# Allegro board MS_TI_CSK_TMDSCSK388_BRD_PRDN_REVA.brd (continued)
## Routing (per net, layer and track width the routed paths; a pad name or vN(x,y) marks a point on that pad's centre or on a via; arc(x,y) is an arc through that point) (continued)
DM388_DDR0_A1: length 50.2
  TOP w0.102: U6.P7 23.38,18.69 23.1,18.69 v1(22.8,19) 22.21,19.58 21.11,19.58 20.93,19.4 RA4.7 ; U7.AC22 44.07,13.84 43.89,14.02 v1(43.89,14.27) ; U8.P7 v1(23.51,8.39)
  L03_SIG1 w0.102: v1(23.51,8.39) 23.51,7.59 23.91,7.2 23.91,5.84 26.24,3.51 36.71,3.51 36.96,3.51 38.56,5.1 38.56,6.67 38.69,6.8 38.69,7.11 39.25,7.67 39.25,7.86 39.21,7.89 39.21,8.21 39.44,8.43 39.84,8.43 39.99,8.43 40.19,8.23 41.6,8.23 43.64,10.27 43.64,12.22 43.97,12.55 43.97,14.19 v1(43.89,14.27)
  L06_SIG2 w0.102: v1(22.8,19) 21.53,17.73 21.53,10.37 v1(23.51,8.39)
DM388_DDR0_A2: length 49.9
  TOP w0.102: U6.P3 v1(23.51,21.75) ; v1(41.56,13.8) 41.48,13.72 U7.AJ23 ; U8.P3 v1(23.51,11.59)
  L06_SIG2 w0.102: v1(23.51,21.75) 23.82,21.45 23.97,21.45 24.06,21.36 24.06,21.09 23.99,21.02 23.04,21.02 22.94,20.91 22.94,20.71 23.04,20.61 23.41,20.61 23.51,20.51 23.51,18.64 23.93,18.23 23.93,14.91 23.84,14.83 23.66,14.83 23.58,14.74 23.58,14.61 23.66,14.52 23.84,14.52 23.93,14.43 23.93,12.01 v1(23.51,11.59) 23.51,10.27 24.98,8.8 24.98,8.1 25.09,8 26.22,8 26.34,7.87 26.34,7.39 26.45,7.29 26.65,7.29 26.75,7.39 26.75,7.85 26.85,7.95 27.05,7.95 27.16,7.85 27.16,7.39 27.26,7.29 27.46,7.29 27.56,7.39 27.56,7.85 27.66,7.95 27.9,7.95 28,7.85 28,5.89 28.1,5.79 28.3,5.79 28.4,5.89 28.4,7.13 28.51,7.23 28.82,7.23 28.92,7.13 28.92,6.6 29.02,6.5 29.22,6.5 29.33,6.6 29.33,7.13 29.43,7.23 30.45,7.23 30.55,7.13 30.55,6.58 30.66,6.48 30.86,6.48 30.96,6.58 30.96,7.13 31.06,7.23 33.07,7.23 37.15,11.32 38.94,11.32 39.06,11.2 40.29,11.2 40.49,11.41 40.49,12.52 41.15,13.18 41.15,13.39 v1(41.56,13.8)
  BOTTOM w0.102: v1(23.51,21.75) 23.35,21.58 23.35,21.31 22.91,20.88 22.18,20.88 21.83,20.53 RA7.7
DM388_DDR0_A3: length 49.8
  TOP w0.102: U6.N2 v1(24.31,22.55) ; v1(41.45,10.87) 41.48,10.9 U7.AJ27 ; U8.N2 v1(24.31,12.39)
  L03_SIG1 w0.102: v1(24.31,12.39) 24.31,12.42 24.7,12.8 24.7,13.49 23.93,14.25 23.93,14.75 23.83,14.85 23.51,14.85 23.41,14.95 23.41,15.16 23.51,15.26 23.83,15.26 23.93,15.36 23.93,20.53 24.04,20.64 24.57,20.64 24.67,20.74 24.67,20.94 24.57,21.04 24.04,21.04 23.93,21.14 23.93,22.17 v1(24.31,22.55)
  BOTTOM w0.102: v1(24.31,12.39) 23.93,12.01 23.93,10.06 24.24,9.75 27.09,9.75 27.49,10.15 28.26,10.15 28.73,9.68 29.9,9.68 32.21,7.37 32.52,7.37 32.7,7.19 32.7,5.77 32.26,5.33 32.26,4.37 32.36,4.27 37.77,4.27 37.9,4.4 37.9,4.65 37.8,4.75 37.57,4.75 37.47,4.85 37.47,5.05 37.57,5.15 37.83,5.15 37.93,5.25 37.93,5.46 37.83,5.56 37.6,5.56 37.49,5.66 37.49,5.86 37.6,5.97 37.86,5.97 37.95,6.06 37.95,6.28 37.86,6.37 37.55,6.37 37.44,6.47 37.44,6.86 37.42,6.89 37.42,8.07 39.92,10.57 40.59,10.57 40.6,10.56 41.14,10.56 v1(41.45,10.87) ; v1(24.31,22.55) 24.46,22.55 24.57,22.45 24.57,22.28 24.46,22.18 24.06,22.18 23.91,22.33 23.91,23.58 23.77,23.71 RA8.6
DM388_DDR0_A4: length 49.9
  TOP w0.102: U7.AK28 40.01,10.84 39.25,10.07 39.25,10.06 39.25,9.91 39.25,9.91 39.25,9.37 38.77,8.89 38.65,8.89 38.01,8.25 38.01,8.23 37.65,7.87 37.65,6.69 37.88,6.46 38.1,6.46 38.21,6.56 v1(38.21,7.21) ; U8.P8 v1(24.31,6.79) ; U6.P8 v1(23.49,17.78)
  L03_SIG1 w0.102: v1(24.31,6.79) 24.31,6.53 24.7,6.15 24.7,5.56 24.89,5.36 25.04,5.36 25.14,5.47 25.29,5.47 25.43,5.33 25.43,5.18 25.33,5.07 25.33,4.93 25.47,4.79 25.61,4.79 25.72,4.89 25.86,4.89 26.01,4.75 26.01,4.61 25.9,4.5 25.9,4.36 26.04,4.22 26.17,4.22 26.29,4.34 26.47,4.34 26.61,4.2 26.61,4.06 26.54,3.98 26.54,3.91 26.64,3.81 36.83,3.81 38.08,5.06 38.08,6.66 37.32,7.41 37.32,7.58 37.44,7.7 37.78,7.7 37.88,7.8 37.88,8.24 38.41,8.76 38.89,8.76 38.99,8.66 38.99,7.85 38.65,7.5 38.4,7.5 38.21,7.31 v1(38.21,7.21)
  L06_SIG2 w0.102: v1(24.31,6.79) 24.7,7.17 24.7,8.63 23.1,10.23 23.1,14.59 23.01,14.68 22.7,14.68 22.61,14.77 22.61,14.9 22.7,14.99 23.01,14.99 23.1,15.08 23.1,17.38 v1(23.49,17.78)
  BOTTOM w0.102: RA11.5 19.96,17.77 20.23,18.03 21.01,18.03 21.27,17.78 v1(23.49,17.78)
DM388_DDR0_A5: length 49.7
  TOP w0.102: U6.P2 v1(23.51,22.55) ; U7.AH27 41.86,11.22 41.86,10.7 v1(41.47,10.31) ; U8.P2 v1(23.51,12.39)
  L03_SIG1 w0.102: v1(23.51,22.55) 23.1,22.13 23.1,21.59 23.25,21.43 23.25,21.2 23.15,21.1 22.76,21.1 22.66,21 22.66,20.8 22.76,20.69 23.15,20.69 23.25,20.59 23.25,20.39 23.15,20.29 22.76,20.29 22.66,20.19 22.66,19.98 22.76,19.88 23.15,19.88 23.25,19.78 23.25,18.43 23.1,18.27 23.1,14.52 23.9,13.72 23.9,12.77 v1(23.51,12.39)
  BOTTOM w0.102: v1(23.51,22.55) 23.6,22.55 23.7,22.45 23.7,22.31 23.6,22.21 23.24,22.21 23.13,22.31 23.13,22.32 23.1,22.36 23.1,22.74 23.13,22.78 23.13,23.57 23.27,23.71 RA8.7 ; v1(41.47,10.31) 40.09,10.31 37.72,7.94 37.72,7.01 38.26,6.48 38.26,4.12 38.1,3.96 32.11,3.96 31.91,4.17 31.91,7.11 29.7,9.32 28.6,9.32 28.43,9.5 28.43,9.51 28.08,9.86 27.6,9.86 27.26,9.51 27.26,9.5 27.16,9.4 23.32,9.4 23.13,9.59 23.13,12.01 v1(23.51,12.39)
DM388_DDR0_A6: length 49.6
  TOP w0.102: U7.AK30 40.98,9.25 40.08,8.36 39.9,8.36 v1(39.6,8.05) ; U6.R8 v1(22.71,16.95) ; U8.R8 v1(22.71,6.79)
  L03_SIG1 w0.102: v1(39.6,8.05) 39.6,7.59 39.02,7.01 39.02,6.7 38.86,6.55 38.86,4.98 37.09,3.2 36.58,3.2 25.45,3.2 25.35,3.3 25.35,3.86 25.25,3.96 25.05,3.96 24.95,3.86 24.95,3.3 24.85,3.2 24.64,3.2 24.54,3.3 24.54,4.73 24.44,4.83 24.24,4.83 24.13,4.73 24.13,3.3 24.03,3.2 23.8,3.2 23.7,3.3 23.7,4.78 23.6,4.88 23.37,4.88 23.3,4.8 23.3,4.19 23.19,4.09 22.91,4.09 22.81,4.19 22.81,5.41 23.12,5.72 23.12,6.39 v1(22.71,6.79) 23.1,7.17 23.1,9.47 22.99,9.57 22.1,9.57 22,9.67 22,9.87 22.1,9.98 22.99,9.98 23.1,10.08 23.1,13.51 22.33,14.27 22.33,16.31 22.71,16.69 v1(22.71,16.95)
  BOTTOM w0.102: v1(22.71,16.95) 22.33,17.33 21.73,17.33 21.42,17.02 21.42,16.92 20.77,16.27 RA11.8
DM388_DDR0_A7: length 49.8
  TOP w0.102: v1(42.76,13.8) 42.48,13.51 U7.AG23 ; U6.R2 v1(22.71,22.55) ; U8.R2 v1(22.71,12.39)
  L03_SIG1 w0.102: v1(22.71,22.55) 22.3,22.13 22.3,19.98 22.12,19.8 21.7,19.8 21.59,19.7 21.59,19.5 21.7,19.4 22.19,19.4 22.3,19.29 22.3,16.79 22.03,16.53 21.57,16.53 21.42,16.38 21.42,14.05 21.89,13.57 22.07,13.57 22.3,13.35 22.3,13.04 22.71,12.62 v1(22.71,12.39)
  BOTTOM w0.102: v1(22.71,22.55) 22.33,22.93 22.33,23.7 22.16,23.88 22.05,23.88 21.95,23.98 21.95,24.33 22.05,24.44 22.31,24.44 22.42,24.32 RA8.8 ; v1(42.76,13.8) 42.38,13.41 40.66,13.41 40.57,13.5 40.57,13.77 40.49,13.86 40.36,13.86 40.27,13.77 40.27,13.5 40.18,13.41 39.91,13.41 39.82,13.5 39.82,13.73 39.73,13.82 39.6,13.82 39.51,13.73 39.51,13.5 39.42,13.41 36.34,13.41 36.19,13.56 36.19,14.37 36.02,14.54 35.9,14.54 35.8,14.64 35.8,15.69 35.69,15.79 35.49,15.79 35.39,15.69 35.39,14.65 35.28,14.54 35.12,14.54 35.03,14.63 35.03,15.6 34.94,15.69 34.81,15.69 34.72,15.6 34.72,14.7 34.56,14.54 34.44,14.54 34.35,14.63 34.35,14.83 34.26,14.92 34.13,14.92 34.04,14.83 34.04,14.63 33.95,14.54 33.83,14.54 33.74,14.63 33.74,14.83 33.65,14.92 33.52,14.92 33.43,14.83 33.43,14.63 33.34,14.54 32.3,14.54 32.21,14.63 32.21,15.48 32.12,15.57 31.99,15.57 31.9,15.48 31.9,14.63 31.81,14.54 22.49,14.54 22.28,14.34 22.28,13.54 22.33,13.49 22.33,12.78 v1(22.71,12.39)
DM388_DDR0_A8: length 49.4
  TOP w0.102: U8.T8 v1(21.91,6.79) ; v1(39.35,6.34) 39.04,6.64 39.04,8.13 39.65,8.75 39.65,9.43 39.65,9.43 39.65,9.74 39.65,9.74 39.65,9.9 40.1,10.34 U7.AL29 ; RA4.5 19.81,17.33 20.17,16.97 21.9,16.97 v1(21.91,16.95) U6.T8
  L03_SIG1 w0.102: v1(21.91,6.79) 22.33,6.38 22.33,4.09 23.52,2.9 36.46,2.9 37.21,2.9 38.79,4.47 40.31,4.47 40.82,4.98 40.82,5.79 40.57,6.04 40.57,7.32 40.46,7.42 40.21,7.42 40.11,7.32 40.11,6.68 39.98,6.56 39.98,6.54 39.78,6.34 v1(39.35,6.34)
  BOTTOM w0.102: v1(21.91,16.95) 21.06,16.1 21.06,9.96 21.16,9.86 21.85,9.86 21.95,9.76 21.95,9.56 21.85,9.45 21.16,9.45 21.06,9.35 21.06,7.06 21.33,6.79 v1(21.91,6.79)
DM388_DDR0_A9: length 49.6
  TOP w0.102: v1(38.45,7.99) 38.94,8.48 38.94,8.65 39.45,9.16 39.45,9.34 39.45,9.98 39.45,9.99 40.09,10.64 40.68,10.64 U7.AK29 ; U6.R3 v1(22.71,21.75) ; U8.R3 v1(22.71,11.59)
  L06_SIG2 w0.102: v1(22.71,11.59) 22.69,11.59 22.31,11.97 22.31,17.42 23.2,18.31 23.2,19.42 23.09,19.52 22.38,19.52 22.28,19.62 22.28,19.83 22.38,19.93 22.92,19.93 23.02,20.03 23.02,20.23 22.92,20.34 22.38,20.34 22.28,20.44 22.28,20.64 22.71,21.08 v1(22.71,21.75)
  BOTTOM w0.102: v1(22.71,11.59) 22.71,9.04 22.84,8.92 27.28,8.92 27.46,9.09 27.46,9.43 27.68,9.65 28,9.65 28.22,9.43 28.22,9.09 28.32,8.99 28.86,8.99 29.13,8.72 29.13,8.21 30.15,7.19 30.82,7.19 31.12,6.89 31.12,4.06 31.53,3.66 38.23,3.66 38.76,4.18 38.76,7.68 v1(38.45,7.99) ; RA7.6 22.04,21.03 22.22,21.21 22.87,21.21 23.02,21.36 23.02,21.92 22.91,22.02 22.79,22.02 22.69,21.92 22.69,21.78 v1(22.71,21.75)
DM388_DDR0_A10: length 49.4
  TOP w0.102: v1(43.53,13.82) 43.98,13.37 U7.AD23 ; U6.L7 v1(25.91,17.75) ; U8.L7 v1(25.91,7.59)
  L03_SIG1 w0.102: v1(25.91,7.59) 25.91,8.02 25.91,8.03 25.91,10.16 27.11,11.35 27.11,13.46 26.66,13.91 26.66,15.48 26.33,15.81 26.33,18.42 26.23,18.52 26.02,18.52 25.91,18.42 v1(25.91,17.75)
  L06_SIG2 w0.102: v1(43.53,13.82) 43.53,13.24 42.76,12.47 41.51,12.47 41.51,12.45 41.02,11.96 41.02,11.36 40.31,10.65 37.48,10.65 35.89,9.07 35.89,8.67 35.15,7.93 35.15,5.6 35.13,5.59 35.13,4.47 35.01,4.35 25.24,4.35 25.14,4.45 25.14,4.95 25.04,5.06 24.84,5.06 24.73,4.95 24.73,4.45 24.63,4.35 24.4,4.35 24.24,4.52 24.24,5.33 24.39,5.49 25.35,5.49 25.53,5.67 25.53,7.21 v1(25.91,7.59)
  BOTTOM w0.102: RA10.8 25.12,19.37 25.02,19.27 25.02,19.1 25.12,19 25.76,19 26.08,18.68 26.08,18.53 25.91,18.37 v1(25.91,17.75)
DM388_DDR0_A11: length 48.3
  TOP w0.102: U7.AK24 40.69,12.55 39.7,12.55 39.42,12.83 39.35,12.83 39.04,12.83 38.33,12.12 v1(38.33,10.14) ; U6.R7 22.65,18.62 22.64,18.62 22.55,18.71 22.12,18.71 21.95,18.54 v1(21.52,18.54) 21.16,18.9 RA4.6 ; U8.R7 v1(22.71,8.39)
  L06_SIG2 w0.102: v1(21.52,18.54) 21.11,18.14 21.11,9.25 21.97,8.39 v1(22.71,8.39) 22.33,8.01 22.33,5.26 22.36,5.23 22.36,5 22.24,4.88 21.89,4.88 21.77,4.76 21.77,4.52 21.89,4.4 22.24,4.4 22.36,4.28 22.36,3.91 22.54,3.73 36.39,3.73 37.22,4.56 37.22,9.3 37.16,9.37 37.16,9.78 37.51,10.14 v1(38.33,10.14)
DM388_DDR0_A12: length 51.8
  TOP w0.102: U6.N7 24.86,18.3 24.86,18.61 ; 24.86,18.61 v1(24.91,18.65) ; 24.86,18.61 24.6,18.61 23.31,19.9 RA4.8 ; U7.AH23 41.98,13.58 v1(42.19,13.8) ; U8.N7 v1(24.31,8.39)
  L03_SIG1 w0.102: v1(24.91,18.65) 24.91,18.88 24.9,18.89 24.9,18.9 24.77,19.03 24.54,19.03 24.44,18.92 24.44,17.4 24.73,17.1 24.73,16.76 24.96,16.53 25.27,16.53 25.5,16.31 25.5,15.5 25.84,15.16 25.84,12.85 25.53,12.55 25.53,9.61 v1(24.31,8.39) 25.53,7.18 25.53,6.6 26.03,6.11 26.03,5.73 27.33,4.43 36.51,4.43 37.28,5.2 37.46,5.37 37.46,6.41 36.68,7.19 36.68,8.18 37.6,9.09 37.85,9.09 38.18,9.42 38.56,9.42 39.15,10.01 40.31,10.01 40.52,9.81 40.52,8.87 40.69,8.69 41.48,8.69 43.23,10.44 43.23,12.76 v1(42.19,13.8)
DM388_DDR0_A13: length 50.3
  TOP w0.102: v1(36.73,9.07) 37.05,9.39 37.05,9.72 37.35,10.02 37.35,12.15 38.99,13.79 40.52,13.79 U7.AK23 ; U6.T3 v1(21.91,21.75) ; U8.T3 v1(21.91,11.59)
  L03_SIG1 w0.102: v1(21.91,21.75) 21.14,20.97 21.14,20.77 21.24,20.67 21.47,20.67 21.57,20.57 21.57,20.36 21.47,20.26 21.26,20.26 21.14,20.14 21.14,18.22 21.33,18.03 21.33,17 20.86,16.53 20.86,12.93 20.98,12.81 22.03,12.81 22.3,12.55 22.3,11.97 v1(21.91,11.59)
  L06_SIG2 w0.102: v1(21.91,11.59) 21.91,10.86 23.9,8.88 23.9,4.4 24.26,4.04 35.31,4.04 35.44,4.17 35.44,7.77 v1(36.73,9.07)
  BOTTOM w0.102: RA7.5 20.62,21.53 20.54,21.6 20.54,21.89 20.71,22.06 21.68,22.06 21.77,22.15 22.2,22.15 22.31,22.05 22.31,21.82 22.2,21.72 21.95,21.72 v1(21.91,21.75)
DM388_DDR0_A14: length 48.1
  TOP w0.102: v1(20.66,17.63) 21.79,17.63 U6.T7 ; U7.AL23 40.28,13.54 39.2,13.54 37.83,12.17 37.83,9.76 v1(37.65,9.58) ; U8.T7 v1(21.91,7.59)
  L03_SIG1 w0.102: v1(20.66,17.63) 20.22,17.19 20.22,16.87 20.2,16.84 20.2,8.48 21.09,7.59 v1(21.91,7.59)
  L06_SIG2 w0.102: v1(37.65,9.58) 37.65,4.42 36.58,3.35 22.15,3.35 21.11,4.4 21.11,7.27 21.44,7.59 v1(21.91,7.59)
  BOTTOM w0.102: RA11.6 20.39,17.27 20.52,17.14 20.66,17.14 20.96,17.43 20.96,17.58 20.86,17.68 20.71,17.68 v1(20.66,17.63)
DM388_DDR0_BA0: length 49.2
  TOP w0.102: U7.AK26 40.68,12.14 39.84,12.14 v1(39.32,11.62) ; U8.M2 v1(25.11,12.39) ; U6.M2 v1(25.11,22.55)
  L06_SIG2 w0.102: v1(39.32,11.62) 37,11.62 33.38,8 32.68,8 32.58,7.9 32.58,7.62 32.48,7.52 32.28,7.52 32.17,7.62 32.17,7.9 32.07,8 31.87,8 31.77,7.9 31.77,7.62 31.67,7.52 31.46,7.52 31.36,7.62 31.36,7.9 31.26,8 30.23,8 30.13,7.9 30.13,7.62 30.03,7.52 29.83,7.52 29.73,7.62 29.73,7.9 29.63,8 29.26,8 29.13,8.13 29.13,8.77 28.88,9.02 28.4,9.02 28.3,9.12 28.3,9.58 28.15,9.73 27.44,9.73 27.33,9.63 27.33,8.92 27.23,8.81 25.99,8.81 25.89,8.71 25.89,8.41 25.78,8.31 25.58,8.31 25.48,8.41 25.48,8.99 25.38,9.09 25.2,9.09 25.1,9.2 25.1,9.4 25.2,9.5 25.38,9.5 25.48,9.6 25.48,9.83 25.38,9.93 24.24,9.93 24.11,10.07 24.11,10.21 24.21,10.31 25.66,10.31 25.73,10.39 25.73,10.59 25.62,10.7 23.93,10.7 23.83,10.8 23.83,11.01 23.93,11.11 24.62,11.11 24.72,11.21 24.72,11.97 25.11,12.37 v1(25.11,12.39) 25.11,12.54 25.51,12.93 25.51,14.22 25.42,14.31 25.25,14.31 25.16,14.4 25.16,14.52 25.25,14.61 25.42,14.61 25.51,14.7 25.51,14.83 25.42,14.92 25.25,14.92 25.16,15 25.16,15.13 25.25,15.22 25.42,15.22 25.51,15.31 25.51,18.05 25.5,18.06 25.5,18.76 24.73,19.52 24.73,20.04 24.84,20.14 25.33,20.14 25.43,20.24 25.43,20.45 25.33,20.55 24.84,20.55 24.73,20.65 24.73,22.17 v1(25.11,22.55)
  BOTTOM w0.102: v1(25.11,22.55) 24.72,22.95 24.72,24.64 24.62,24.74 24.35,24.74 24.27,24.67 RA8.5
DM388_DDR0_BA1: length 51.7
  TOP w0.102: v1(42.77,14.4) 43.15,14.02 43.15,13.51 U7.AF23 ; U8.N8 v1(24.31,7.59) ; U6.N8 v1(24.31,16.95)
  L03_SIG1 w0.102: v1(24.31,16.95) 24.31,16.69 24.72,16.29 24.72,15.19 24.82,15.09 25.25,15.09 25.38,14.96 25.38,14.71 25.28,14.61 24.49,14.61 24.39,14.5 24.39,14.28 24.59,14.07 25.3,14.07 25.53,13.84 25.53,13.07 25.23,12.77 24.96,12.77 24.7,12.51 24.7,10.04 23.93,9.27 23.93,7.97 v1(24.31,7.59) 24.7,7.21 24.7,6.63 24.96,6.37 25.27,6.37 25.61,6.03 25.61,5.66 27.15,4.12 36.63,4.12 37.76,5.25 37.76,6.09 37.76,6.54 36.99,7.32 36.99,7.95 37.82,8.79 37.97,8.79 38.25,9.07 39.49,9.07 39.92,8.64 40.21,8.64 40.42,8.43 41.52,8.43 43.44,10.35 43.44,13.13 43.15,13.42 43.15,14.02 v1(42.77,14.4)
  BOTTOM w0.102: RA11.7 20.39,16.77 20.52,16.64 20.63,16.64 21.54,17.55 23.12,17.55 23.72,16.95 v1(24.31,16.95)
DM388_DDR0_BA2: length 49.4
  TOP w0.102: v1(42.13,11.83) 41.98,11.98 U7.AH25 ; U6.M3 v1(25.11,21.75) ; U8.M3 v1(25.11,11.59)
  L06_SIG2 w0.102: v1(25.11,21.75) 25.71,21.16 25.71,20.68 25.81,20.58 26.17,20.58 26.27,20.47 26.27,20.27 26.17,20.17 25.81,20.17 25.71,20.07 25.71,19.87 25.81,19.76 26.17,19.76 26.27,19.66 26.27,19.46 26.17,19.36 25.81,19.36 25.71,19.26 25.71,18.97 26.3,18.39 26.3,16.77 25.82,16.29 25.82,13.72 25.72,13.62 25.72,12.84 25.51,12.63 25.51,11.98 v1(25.11,11.59)
  BOTTOM w0.102: v1(25.11,11.59) 24.67,11.15 24.41,11.15 24.31,11.05 24.31,10.24 24.51,10.03 26.94,10.03 27.26,10.35 29.68,10.35 32.39,7.65 34.09,7.65 34.33,7.4 34.33,5.83 34.7,5.46 34.7,4.68 34.8,4.57 35.03,4.57 35.13,4.68 35.13,5.28 35.23,5.39 35.44,5.39 35.54,5.28 35.54,4.68 35.64,4.57 35.85,4.57 35.95,4.68 35.95,5.28 36.05,5.39 36.25,5.39 36.36,5.28 36.36,4.68 36.46,4.57 37.01,4.57 37.15,4.71 37.15,6.33 37.11,6.37 37.11,8.19 39.84,10.92 40.64,10.92 41.1,11.38 41.68,11.38 v1(42.13,11.83) ; v1(25.11,21.75) 25.12,21.74 25.12,21.54 25.02,21.44 24.9,21.44 24.74,21.59 24.74,22.05 24.85,22.15 25.45,22.15 25.53,22.07 25.53,21.42 25.65,21.3 RA10.5
DM388_DDR0_CASN: length 49
  TOP w0.102: U6.K3 v1(26.71,21.75) ; U7.AK25 39.33,12.34 39.22,12.45 v1(39.2,12.45) ; U8.K3 v1(26.71,11.59)
  L06_SIG2 w0.102: v1(26.71,11.59) 26.33,11.97 26.33,13.38 27.44,14.48 27.44,14.68 27.56,14.8 27.78,14.8 27.9,14.92 27.9,15.77 27.79,15.87 27.4,15.87 27.3,15.97 27.3,16.18 27.4,16.28 27.79,16.28 27.9,16.38 27.9,16.61 27.79,16.71 27.74,16.71 27.64,16.81 27.64,17.01 27.74,17.12 27.79,17.12 27.9,17.22 27.9,18.47 27.61,18.75 27.61,20.42 26.71,21.32 v1(26.71,21.75)
  BOTTOM w0.102: RA6.7 25.94,23.36 26.32,22.99 26.32,21.87 26.44,21.75 v1(26.71,21.75) ; v1(39.2,12.45) 38.76,12.45 38.59,12.27 38.59,11.66 38.48,11.56 38.08,11.56 37.98,11.66 37.98,12.61 37.88,12.71 37.55,12.71 37.44,12.6 37.44,11.02 37.27,10.85 37.06,10.85 36.99,10.92 36.99,12.19 36.88,12.29 36.66,12.29 36.55,12.19 36.55,10.39 36.45,10.29 36.16,10.29 36.06,10.39 36.06,11.41 35.96,11.51 35.75,11.51 35.65,11.41 35.65,10.39 35.55,10.29 35.28,10.29 35.18,10.39 35.18,10.64 35.08,10.75 34.87,10.75 34.77,10.64 34.77,10.39 34.67,10.29 34.44,10.29 34.34,10.39 34.34,11.08 34.24,11.18 34.04,11.18 33.93,11.08 33.93,10.39 33.83,10.29 33.63,10.29 33.53,10.39 33.53,11.08 33.43,11.18 33.22,11.18 33.12,11.08 33.12,10.39 33.02,10.29 32.82,10.29 32.71,10.39 32.71,11.08 32.61,11.18 32.41,11.18 32.31,11.08 32.31,9.85 32.24,9.78 31.96,9.78 31.86,9.88 31.86,11.08 31.75,11.18 31.53,11.18 31.42,11.08 31.42,10.34 31.32,10.24 31.12,10.24 31,10.35 31,11.02 30.9,11.13 27.18,11.13 v1(26.71,11.59)
DM388_DDR0_CKE: length 50.3
  TOP w0.102: U6.K9 v1(26.71,16.15) ; v1(43.33,14.4) 43.44,14.4 43.69,14.65 43.79,14.65 U7.AD20 ; U8.K9 v1(26.71,5.99)
  L03_SIG1 w0.102: v1(26.71,16.15) 27.02,15.85 27.02,15.63 27.18,15.47 27.41,15.47 27.51,15.37 27.51,15.04 27.41,14.94 27.07,14.94 26.97,14.84 26.97,14.64 27.07,14.54 27.34,14.54 27.44,14.43 27.44,13.55 27.51,13.47 27.51,13.08 27.94,12.65 27.94,11.18 26.33,9.57 26.33,8 27.13,7.2 27.13,6.41 v1(26.71,5.99)
  L06_SIG2 w0.102: v1(43.33,14.4) 43.21,14.28 43.21,14.12 43.15,14.07 43.15,13.44 42.69,12.98 41.38,12.98 40.69,12.29 40.69,11.32 40.3,10.92 39.03,10.92 38.94,11.01 37.28,11.01 34.33,8.07 34.33,4.87 34.12,4.66 29.34,4.66 29.24,4.76 29.24,5.28 29.14,5.39 28.93,5.39 28.83,5.28 28.83,4.76 28.73,4.66 28.53,4.66 28.43,4.76 28.43,5.28 28.32,5.39 28.12,5.39 28.02,5.28 28.02,4.76 27.92,4.66 27.72,4.66 27.61,4.76 27.61,5.28 27.51,5.39 27.31,5.39 27.21,5.28 27.21,4.76 27.11,4.66 26.9,4.66 26.8,4.76 26.8,5.28 26.7,5.39 26.5,5.39 26.39,5.28 26.39,4.76 26.29,4.66 26.06,4.66 25.91,4.81 25.91,5.87 26.04,5.99 v1(26.71,5.99)
  BOTTOM w0.102: RA10.7 25.91,19.87 26.32,19.46 26.32,16.55 v1(26.71,16.15)
DM388_DDR0_CLK: length 49.9
  TOP w0.102: U6.J7 v1(27.51,17.75) ; U8.J7 v1(27.51,8.39) ; U7.AL27 39.71,11.34 39.64,11.26 39.49,11.26 38.82,10.59 38.82,9.94 38.48,9.6 38.35,9.6 36.89,8.13 35.46,8.13 35.2,7.86 35.2,7.28 35.46,7.01 36.74,7.01 36.89,6.86 36.89,6.41 37.16,6.14 37.16,4.39 37.04,4.27 34.13,4.27 34.03,4.37 34.03,4.63 34.16,4.75 35.89,4.75 36.17,5.03 36.17,5.46 36.23,5.51 36.71,5.51 36.78,5.59 36.78,5.78 v1(36.67,5.89)
  L03_SIG1 w0.102: v1(36.67,5.89) 36.62,5.85 36.48,5.85 36.38,5.95 36.38,6.28 36.01,6.66 35.51,6.66 35.18,6.33 35.18,5.65 35.01,5.48 28.53,5.48 28.32,5.68 28.32,7.29 27.81,7.8 27.47,7.8 27.13,8.14 27.13,8.31 27.22,8.39 27.45,8.39 ; v1(27.51,17.75) 27.41,17.75 27.26,17.6 27.26,17.45 28.05,16.66 28.05,15.91 28.32,15.63 29.2,15.63 29.49,15.34 29.49,14.86 29.2,14.57 28.32,14.57 28.25,14.49 28.25,13.84 28.68,13.41 28.68,10.87 27.25,9.44 27.25,8.59 27.45,8.39 ; 27.45,8.39 v1(27.51,8.39)
  BOTTOM w0.102: v1(27.51,17.75) 27.44,17.75 27.33,17.85 27.33,18.15 27.44,18.25 27.92,18.25 28.19,18.51 28.19,18.89 27.97,19.11 27.97,19.33 28.29,19.65 R107.1
DM388_DDR0_CLKN: length 49.9
  TOP w0.102: v1(35.96,5.89) 35.89,5.83 35.89,5.15 35.78,5.03 34.04,5.03 33.75,4.74 33.75,4.25 34.01,3.99 37.15,3.99 37.44,4.28 37.44,6.25 37.17,6.52 37.17,6.98 36.86,7.29 35.58,7.29 35.48,7.39 35.48,7.75 35.58,7.85 37,7.85 38.47,9.32 38.59,9.32 39.02,9.74 39.02,10.44 39.64,11.06 40.7,11.06 U7.AK27 ; U6.K7 v1(26.71,17.75) ; U8.K7 v1(26.71,8.39)
  L03_SIG1 w0.102: v1(26.71,17.75) 26.93,17.54 26.93,17.31 27.72,16.53 27.72,15.78 28.19,15.3 29.06,15.3 29.16,15.2 29.16,14.99 29.07,14.9 28.19,14.9 27.92,14.63 27.92,13.71 28.35,13.28 28.35,11.01 26.92,9.58 26.92,8.55 26.76,8.39 v1(26.71,8.39) 26.8,8.31 26.8,8 27.33,7.47 27.68,7.47 27.99,7.15 27.99,5.54 28.39,5.15 35.15,5.15 35.51,5.51 35.51,6.19 35.65,6.33 35.87,6.33 36.05,6.15 36.05,5.98 v1(35.96,5.89)
  BOTTOM w0.102: R108.1 27.42,19.65 27.69,19.38 27.69,18.99 27.91,18.77 27.91,18.63 27.81,18.53 27.32,18.53 27.05,18.26 27.05,17.96 26.85,17.75 v1(26.71,17.75)
DM388_DDR0_CS0N: length 49.4
  TOP w0.102: U7.AB21 44.51,14.34 v1(44.47,14.3) ; U8.L2 v1(25.91,12.39) ; U6.L2 v1(25.91,22.55)
  L06_SIG2 w0.102: v1(25.91,22.55) 26.3,22.17 26.3,21.24 27.1,20.44 27.1,20.09 26.99,19.99 26.67,19.99 26.57,19.89 26.57,19.68 26.67,19.58 26.99,19.58 27.1,19.48 27.1,19.28 26.99,19.18 26.67,19.18 26.57,19.07 26.57,18.87 26.67,18.77 26.99,18.77 27.1,18.67 27.1,15.85 26.72,15.47 26.72,14.29 25.93,13.51 25.93,12.41 v1(25.91,12.39)
  BOTTOM w0.102: v1(25.91,22.55) 25.56,22.91 25.56,23.5 25.33,23.72 25.23,23.72 25.02,23.93 25.02,24.56 25.15,24.69 25.33,24.69 25.44,24.58 RA6.8 ; v1(44.47,14.3) 44.17,13.99 44.17,12.72 43.82,12.37 41.38,12.37 40.25,11.24 39.6,11.24 39.31,10.95 38.28,10.95 37.16,9.83 37.16,9.38 37.21,9.33 37.21,8.73 36.81,8.32 36.81,6.49 36.71,6.39 36.35,6.39 36.25,6.49 36.25,7.93 36.15,8.03 35.92,8.03 35.82,7.93 35.82,7.11 35.72,7.01 35.51,7.01 35.41,7.11 35.41,7.93 35.31,8.03 32.47,8.03 32.36,8.13 32.36,8.92 32.02,9.26 31.3,9.26 30,10.55 26.86,10.55 26.7,10.39 25.64,10.39 25.53,10.49 25.53,12.01 v1(25.91,12.39)
DM388_DDR0_DQ0: length 18.5
  TOP w0.102: U7.AL9 40.21,20.61 39.15,20.61 38.99,20.45 33.63,20.45 33.49,20.58 33.49,20.8 33.39,20.91 33.19,20.91 33.09,20.8 33.09,20.58 32.99,20.48 32.78,20.48 32.68,20.58 32.68,20.8 32.58,20.91 32.37,20.91 32.27,20.8 32.27,20.58 32.17,20.48 31.97,20.48 31.86,20.58 31.86,20.8 31.76,20.91 31.56,20.91 31.46,20.8 31.46,20.58 30.86,19.99 28.25,19.99 28.15,20.09 28.15,20.27 28.25,20.37 30.63,20.37 31.11,20.85 U6.E3
DM388_DDR0_DQ1: length 18.9
  TOP w0.102: v1(38.04,19.82) 38.35,20.12 39,20.12 39.15,20.27 40.06,20.27 40.27,20.06 40.7,20.06 U7.AK9 ; U6.F7 v1(30.31,19.18)
  L03_SIG1 w0.102: v1(30.31,19.18) 30.08,18.94 30.08,18.8 30.15,18.72 31.32,18.72 31.83,19.23 31.83,19.61 31.93,19.71 32.14,19.71 32.24,19.61 32.24,19.41 32.34,19.3 32.54,19.3 32.64,19.41 32.64,19.61 32.75,19.71 32.95,19.71 33.05,19.61 33.05,19.41 33.15,19.3 33.36,19.3 33.46,19.41 33.46,19.61 33.56,19.71 33.76,19.71 33.86,19.61 33.86,19.41 33.97,19.3 34.17,19.3 34.27,19.41 34.27,19.61 34.37,19.71 34.57,19.71 34.68,19.61 34.68,19.41 34.78,19.3 35.23,19.3 35.69,19.76 36.05,19.76 36.15,19.66 36.15,19.49 36.29,19.36 36.46,19.36 36.56,19.46 36.56,19.66 36.66,19.76 36.94,19.76 37.04,19.66 37.04,19.53 37.34,19.23 38.61,19.23 38.76,19.38 38.76,19.97 38.6,20.13 38.12,20.13 38.04,20.06 v1(38.04,19.82)
DM388_DDR0_DQ2: length 18.9
  TOP w0.102: U6.F2 30.74,21.73 30.74,21.06 30.25,20.57 28.02,20.57 27.92,20.47 27.92,19.89 28.02,19.79 31.08,19.79 31.2,19.79 31.55,20.14 36.45,20.14 36.58,20.02 37.16,20.02 37.88,19.3 38.54,19.3 39.02,19.79 39.09,19.79 39.3,19.99 39.96,19.99 40.11,19.84 U7.AK10
DM388_DDR0_DQ3: length 18.7
  TOP w0.102: U7.AJ11 41.48,19.71 v1(41.56,19.79) ; U6.F8 v1(30.69,17.73)
  L03_SIG1 w0.102: v1(41.56,19.79) 41.13,19.79 40,18.67 39.12,18.67 39.07,18.62 37.6,18.62 37.25,18.26 35.69,18.26 35.23,18.72 32.06,18.72 31.5,18.16 30.46,18.16 29.53,17.24 29.53,15.99 29.78,15.75 30.23,15.75 30.33,15.85 30.33,17.37 v1(30.69,17.73)
DM388_DDR0_DQ4: length 18.4
  TOP w0.102: U6.H3 v1(29.11,21.75) ; v1(42.19,19.77) 41.98,19.55 U7.AH11
  L06_SIG2 w0.102: v1(42.19,19.77) 41.83,19.41 41.18,19.41 40.34,20.24 37.32,20.24 37.31,20.25 36.89,20.25 36,21.14 36,21.64 35.21,22.43 35.21,23.55 35.02,23.73 32.96,23.73 32.95,23.72 32.91,23.72 32.7,23.51 32.7,23.19 32.43,22.93 29.76,22.93 29.53,22.71 29.53,22.17 v1(29.11,21.75)
DM388_DDR0_DQ5: length 18.7
  TOP w0.102: U6.H8 v1(29.14,16.93) ; v1(43.91,19.84) 43.98,19.9 U7.AD9
  L03_SIG1 w0.102: v1(29.14,16.93) 29.14,17.36 30.19,18.42 31.4,18.42 32.03,19.05 35.34,19.05 35.74,18.65 37.09,18.65 37.37,18.92 39.94,18.92 40.54,19.53 40.54,19.9 41.4,20.76 42.99,20.76 v1(43.91,19.84)
DM388_DDR0_DQ6: length 18.8
  TOP w0.102: U6.G2 v1(29.91,22.55) ; v1(42.76,19.77) 42.98,19.55 U7.AF11
  L06_SIG2 w0.102: v1(29.91,22.55) 29.91,21.68 30.22,21.37 32.59,21.37 32.73,21.51 32.73,22.75 32.92,22.93 32.96,22.93 34.39,22.93 34.99,22.34 35.34,21.99 35.34,21.87 35.69,21.52 35.69,21.02 35.87,20.84 35.87,20.84 36.76,19.95 37.18,19.95 37.79,19.34 38.24,19.34 38.7,19.8 40.2,19.8 40.8,19.2 41.09,19.2 42.2,19.2 v1(42.76,19.77)
DM388_DDR0_DQ7: length 18.6
  TOP w0.102: U7.AL12 40.32,18.84 40.24,18.92 39.06,18.92 38.99,19 37.72,19 37.05,19.67 36.33,19.67 36.19,19.81 31.65,19.81 31.4,19.56 26.17,19.56 26.01,19.41 26.01,18.8 26.17,18.64 28.22,18.64 U6.H7
DM388_DDR0_DQ8: length 13.8
  TOP w0.102: U7.AJ12 41.48,18.45 v1(41.56,18.37) ; U6.D7 v1(31.54,17.78)
  L03_SIG1 w0.102: v1(31.54,17.78) 31.23,17.47 31.07,17.47 30.94,17.34 30.94,16.82 31.22,16.54 35.67,16.54 36.2,17.07 37.44,17.07 37.87,17.5 40.11,17.5 40.98,18.37 v1(41.56,18.37)
DM388_DDR0_DQ9: length 14.1
  TOP w0.102: U6.C3 v1(33.11,21.75) ; U7.AG12 42.48,18.62 v1(42.73,18.37)
  BOTTOM w0.102: v1(33.11,21.75) 32.77,21.41 32.77,19.43 33.57,18.63 38.94,18.63 39.1,18.79 42.3,18.79 v1(42.73,18.37)
DM388_DDR0_DQ10: length 14
  TOP w0.102: v1(43.84,19.28) 43.98,19.14 U7.AD12 ; U6.C8 v1(33.1,16.97)
  L03_SIG1 w0.102: v1(43.84,19.28) 43.38,18.82 43,18.82 42.9,18.92 42.9,19.18 42.79,19.28 42.59,19.28 42.49,19.18 42.49,18.92 42.39,18.82 42.16,18.82 42.06,18.92 42.06,19.15 41.96,19.25 41.75,19.25 41.65,19.15 41.65,18.92 41.55,18.82 41,18.82 39.98,17.81 37.75,17.81 37.31,17.37 36.73,17.37 34.52,17.37 34.12,16.97 v1(33.1,16.97)
DM388_DDR0_DQ11: length 14.4
  TOP w0.102: U7.AB12 v1(44.55,18.84) ; U6.C2 v1(33.11,22.55)
  L06_SIG2 w0.102: v1(33.11,22.55) 33.53,22.13 34.9,22.13 35.14,21.9 35.14,21.69 35.31,21.51 35.31,20.96 36.64,19.62 37.06,19.62 37.76,18.92 39.06,18.92 39.06,18.92 39.94,18.92 39.97,18.95 43.58,18.95 43.61,18.95 43.69,18.88 43.73,18.84 v1(44.55,18.84)
DM388_DDR0_DQ12: length 13.9
  TOP w0.102: U6.A7 v1(34.71,17.75) ; v1(39.88,18.29) 39.93,18.34 U7.AK13
  L03_SIG1 w0.102: v1(34.71,17.75) 34.28,17.75 33.88,17.35 32.13,17.35 31.98,17.5 31.98,18.26 32.13,18.42 35.06,18.42 35.72,17.75 37.26,17.75 37.8,18.29 v1(39.88,18.29)
DM388_DDR0_DQ13: length 14.2
  TOP w0.102: U6.A2 34.72,21.74 ; v1(43.91,18.37) 43.94,18.34 U7.AC13
  TOP w0.14: 34.72,21.74 v1(34.76,21.74)
  L06_SIG2 w0.102: v1(43.91,18.37) 43.6,18.68 43.53,18.75 43.49,18.75 40.05,18.75 40.02,18.72 39.65,18.72 38.97,18.03 35.31,18.03 35.06,18.28 35.06,21.44 v1(34.76,21.74)
DM388_DDR0_DQ14: length 14
  TOP w0.102: U7.AL14 40.21,17.57 39.65,17.57 39.14,18.09 36.94,18.09 36.73,18.29 36.04,18.29 34.83,19.51 32.59,19.51 32.49,19.41 32.49,19.13 32.39,19.03 32.19,19.03 32.08,19.13 32.08,19.41 31.98,19.51 31.75,19.51 31.65,19.41 31.65,18.75 31.75,18.64 32.21,18.64 32.31,18.54 32.31,17.91 32.47,17.75 33.12,17.75 U6.B8
DM388_DDR0_DQ15: length 14.2
  TOP w0.102: v1(35.79,19.28) 36.22,19.28 36.33,19.17 36.33,18.97 36.71,18.6 36.85,18.6 37.06,18.39 39.22,18.39 39.73,17.88 40.09,17.88 40.34,18.14 40.68,18.14 U7.AK14 ; U6.A3 34.01,21.05
  TOP w0.14: 34.01,21.05 v1(34.01,20.93)
  BOTTOM w0.102: v1(35.79,19.28) 35.49,18.97 34.56,18.97 34.46,19.08 34.46,20.17 34.36,20.27 34.16,20.27 34.06,20.17 34.06,19.08 33.95,18.97 33.71,18.97 33.1,19.58 33.1,20.73 33.3,20.93 v1(34.01,20.93)
DM388_DDR0_DQ16: length 23.7
  TOP w0.102: U8.E3 v1(31.51,11.59) ; U7.AH15 41.98,17.58 v1(42.19,17.8)
  L06_SIG2 w0.102: v1(42.19,17.8) 41.69,17.3 37.39,17.3 37.29,17.2 37.29,15.42 37.19,15.32 33.08,15.32 32.98,15.22 32.98,14.3 32.87,14.2 32.67,14.2 32.57,14.3 32.57,15.22 32.47,15.32 32.26,15.32 32.16,15.22 32.16,14.3 32.06,14.2 31.86,14.2 31.75,14.3 31.75,15.22 31.65,15.32 30.51,15.32 30.33,15.14 30.33,12.24 30.33,12.23 30.33,11.84 30.58,11.59 v1(31.51,11.59)
DM388_DDR0_DQ17: length 23.8
  TOP w0.102: U7.AF15 42.98,17.58 v1(42.76,17.8) ; U8.F7 30.31,8.48 29.62,9.17 28.58,9.17 v1(28.07,8.66)
  L03_SIG1 w0.102: v1(28.07,8.66) 30.31,10.9 30.31,13.51 32.16,15.37 36.64,15.37 38.16,16.89 40.67,16.89 41.15,17.37 42.34,17.37 v1(42.76,17.8)
DM388_DDR0_DQ18: length 23.7
  TOP w0.102: v1(43.91,17.8) 43.98,17.73 U7.AD15 ; U8.F2 v1(30.71,12.39)
  L06_SIG2 w0.102: v1(30.71,12.39) 31.13,12.81 31.13,13.66 31.37,13.89 35.38,13.89 35.48,14 35.48,14.78 35.59,14.89 35.79,14.89 35.89,14.78 35.89,14 35.99,13.89 36.2,13.89 36.3,14 36.3,14.78 36.4,14.89 36.6,14.89 36.71,14.78 36.71,14 36.81,13.89 37.7,13.89 37.92,14.12 37.92,16.73 38.08,16.89 39.8,16.89 39.9,16.79 39.9,16.04 40,15.94 40.2,15.94 40.3,16.04 40.3,16.79 40.56,17.04 43.15,17.04 v1(43.91,17.8)
DM388_DDR0_DQ19: length 23.9
  TOP w0.102: U8.F8 30.74,7.62 31.42,7.62 31.53,7.72 31.53,8.48 31.32,8.69 31.09,8.69 29.87,9.91 29.08,9.91 28.3,10.69 28.3,13.95 29.54,15.19 36.2,15.19 36.68,15.67 36.93,15.67 37.23,15.97 37.23,16.39 37.88,17.04 38.94,17.04 39.15,16.84 U7.AK16
DM388_DDR0_DQ20: length 23.5
  TOP w0.102: v1(41.56,16.39) 41.48,16.47 U7.AJ16 ; U8.H3 v1(29.11,11.59)
  L06_SIG2 w0.102: v1(41.56,16.39) 41.13,16.39 41.05,16.31 41.05,15.72 40.63,15.3 39.05,15.3 38.64,14.89 38.64,13.51 38.26,13.13 36.43,13.13 36.1,12.8 32.99,12.8 32.96,12.77 32.7,12.51 32.7,11.43 32.69,11.43 32.69,10.01 32.49,9.81 31.58,9.81 30.99,10.39 28.96,10.39 28.83,10.52 28.83,10.95 28.73,11.05 28.53,11.05 28.43,10.95 28.43,10.52 28.32,10.41 28.07,10.41 27.87,10.62 27.87,11.35 28.11,11.59 v1(29.11,11.59)
DM388_DDR0_DQ21: length 23.8
  TOP w0.102: v1(42.17,16.39) 42.48,16.69 U7.AG16 ; U8.H8 v1(29.14,7.62)
  L03_SIG1 w0.102: v1(29.14,7.62) 31.48,7.62 31.58,7.72 31.58,8.21 31.68,8.31 31.88,8.31 31.98,8.21 31.98,7.72 32.09,7.62 32.41,7.62 32.57,7.77 32.57,9.4 32.44,9.53 32.03,9.53 31.91,9.65 31.91,13.49 33.1,14.68 36.81,14.68 37.37,15.24 38.65,15.24 39.01,15.6 40.19,15.6 41.36,16.77 41.79,16.77 v1(42.17,16.39)
DM388_DDR0_DQ22: length 23.8
  TOP w0.102: U7.AD16 43.94,16.84 43.5,16.4 v1(43.35,16.4) ; U8.G2 v1(29.91,12.39)
  L06_SIG2 w0.102: v1(43.35,16.4) 42.93,16.82 41,16.82 40.64,16.46 40.64,15.67 40.47,15.5 39.14,15.5 39.14,15.51 38.81,15.51 38.31,15.02 38.31,13.63 38.13,13.45 35.25,13.45 35.06,13.63 34.35,13.63 34.34,13.64 32.16,13.64 31.93,13.41 31.93,11.33 32.44,10.82 32.44,10.19 32.34,10.08 31.83,10.08 31.73,10.19 31.73,10.49 31.53,10.69 30.2,10.69 30.1,10.8 30.1,12.2 v1(29.91,12.39)
DM388_DDR0_DQ23: length 23.6
  TOP w0.102: U8.H7 v1(28.71,8.54) ; U7.AC16 44.48,16.82 v1(44.02,16.36)
  L03_SIG1 w0.102: v1(44.02,16.36) 43.71,16.67 43.71,16.67 43.3,17.07 41.3,17.07 40.77,16.54 38.23,16.54 36.74,15.04 32.67,15.04 31.1,13.47 31.1,8.64 30.54,8.08 29.17,8.08 v1(28.71,8.54)
DM388_DDR0_DQ24: length 15.7
  TOP w0.102: U8.D7 31.91,8.78 31.42,9.28 31.42,9.81 31.52,9.91 31.75,9.91 31.85,9.81 31.85,9.6 31.95,9.5 32.16,9.5 32.26,9.6 32.26,9.81 32.46,10.01 35.77,10.01 36.22,10.47 36.22,12.6 38.59,14.96 38.59,14.96 38.64,15.01 39.13,15.01 39.46,15.34 U7.AK19
DM388_DDR0_DQ25: length 16
  TOP w0.102: v1(41.56,15.79) 41.48,15.72 U7.AJ19 ; U8.C3 v1(33.11,11.59)
  L03_SIG1 w0.102: v1(41.56,15.79) 41.16,15.39 40.01,15.39 38.65,14.04 38.51,14.04 38.21,14.34 38.06,14.34 37.92,14.19 37.92,14.05 38.22,13.75 38.22,13.6 38.08,13.46 37.93,13.46 37.63,13.76 37.49,13.76 37.34,13.62 37.34,13.47 37.65,13.17 37.65,13.03 37.39,12.77 36.91,12.77 36.81,12.87 36.81,13.39 36.7,13.49 36.5,13.49 36.4,13.39 36.4,12.87 36.3,12.77 36.1,12.77 35.99,12.87 35.99,13.39 35.89,13.49 35.69,13.49 35.59,13.39 35.59,12.87 35.49,12.77 33.63,12.77 33.53,12.67 33.53,12.01 v1(33.11,11.59)
DM388_DDR0_DQ26: length 16.1
  TOP w0.102: U8.C8 v1(33.11,6.79) ; v1(42.14,15.8) 42.14,15.5 U7.AH19
  L03_SIG1 w0.102: v1(42.14,15.8) 41.53,15.19 40.26,15.19 37.49,12.42 34.84,12.42 34.4,11.98 34.4,11.33 33.11,10.05 v1(33.11,6.79)
DM388_DDR0_DQ27: length 15.7
  TOP w0.102: v1(42.83,15.67) 42.98,15.52 U7.AF19 ; U8.C2 v1(33.11,12.39)
  L06_SIG2 w0.102: v1(42.83,15.67) 42.83,15.24 42.67,15.08 39.24,15.08 39.02,14.86 39.02,13.34 38.43,12.75 36.73,12.75 36.35,12.37 34.6,12.37 34.32,12.09 34.32,10.97 34.22,10.87 33.62,10.87 33.52,10.97 33.52,11.99 v1(33.11,12.39)
DM388_DDR0_DQ28: length 16.2
  TOP w0.102: v1(43.98,15.8) U7.AD19 ; U8.A7 v1(34.71,7.59)
  L03_SIG1 w0.102: v1(34.71,7.59) 34.71,8.02 34.6,8.14 34.6,11.35 34.86,11.61 37.67,11.61 39.73,13.67 39.88,13.67 40.39,14.17 40.39,14.44 40.94,14.99 43.21,14.99 43.77,15.55 43.77,15.59 v1(43.98,15.8)
DM388_DDR0_DQ29: length 15.6
  TOP w0.102: U7.AC19 44.48,14.91 v1(44.43,14.87) ; U8.A2 v1(34.95,11.99)
  L06_SIG2 w0.102: v1(44.43,14.87) 44,14.87 43.99,14.88 39.45,14.88 39.35,14.78 39.35,13.16 38.61,12.42 36.88,12.42 34.8,10.33 34.64,10.33 34.54,10.44 34.54,11.58 v1(34.95,11.99)
DM388_DDR0_DQ30: length 16.1
  TOP w0.102: v1(41.56,14.37) 41.48,14.45 U7.AJ20 ; U8.B8 v1(33.91,6.79)
  L03_SIG1 w0.102: v1(33.91,6.79) 34.33,7.21 35.61,7.21 35.89,7.49 35.89,9.6 37.26,10.97 40.71,10.97 40.97,11.23 40.97,12.48 41.08,12.58 41.76,12.58 41.86,12.68 41.86,12.89 41.76,12.99 41.08,12.99 40.97,13.09 40.97,13.79 v1(41.56,14.37)
DM388_DDR0_DQ31: length 15.8
  TOP w0.102: U7.AG20 42.48,14.69 v1(42.21,14.43) ; U8.A3 v1(34.98,11.19)
  L03_SIG1 w0.102: v1(34.98,11.19) 34.98,8.71 35.06,8.64 35.36,8.64 35.46,8.74 35.46,9.6 37.13,11.27 39.07,11.27 39.1,11.24 40.35,11.24 40.59,11.48 40.59,14.36 40.99,14.75 41.89,14.75 v1(42.21,14.43)
DM388_DDR0_DQM0: length 18.9
  TOP w0.102: U7.AL8 38.95,20.84 38.89,20.78 36.76,20.78 36.58,20.96 v1(34.67,20.96) ; U6.E7 v1(31.11,19.1)
  L06_SIG2 w0.102: v1(31.11,19.1) 31.11,18.44 31.22,18.34 32.85,18.34 32.95,18.44 32.95,19.69 33.05,19.79 33.25,19.79 33.35,19.69 33.35,18.44 33.46,18.34 33.66,18.34 33.76,18.44 33.76,19.69 33.86,19.79 34.07,19.79 34.17,19.69 34.17,18.44 34.27,18.34 34.5,18.34 34.67,18.52 v1(34.67,20.96)
DM388_DDR0_DQM1: length 14
  TOP w0.102: U6.D3 v1(32.31,21.75) ; v1(36.86,19.13) 37.3,18.7 40.14,18.7 40.29,18.54 40.69,18.54 40.98,18.83 U7.AK12
  BOTTOM w0.102: v1(36.86,19.13) 36.86,19.87 36.76,19.97 35.82,19.97 35.72,20.07 35.72,20.27 35.82,20.38 36.76,20.38 36.86,20.48 36.86,20.78 35.49,22.15 32.71,22.15 v1(32.31,21.75)
DM388_DDR0_DQM2: length 23.6
  TOP w0.102: U7.AJ15 41.48,17.72 v1(41.56,17.8) ; U8.E7 30.78,8.33 30.78,8.55 29.73,9.59 28.16,9.59 v1(27.84,9.27)
  L03_SIG1 w0.102: v1(27.84,9.27) 29.53,10.96 29.53,13.83 31.32,15.62 35.41,15.62 36.55,16.76 37.57,16.76 38,17.2 40.52,17.2 41.13,17.8 v1(41.56,17.8)
DM388_DDR0_DQM3: length 15.7
  TOP w0.102: v1(37.29,14.48) 38.13,15.31 38.86,15.31 39.09,15.55 40.68,15.55 U7.AK18 ; U8.D3 v1(32.31,11.59)
  L03_SIG1 w0.102: v1(32.31,11.59) 32.31,11.16 32.19,11.03 32.19,10.11 32.29,10.01 32.59,10.01 32.73,10.15 32.73,13.69 32.84,13.79 37.04,13.79 37.29,14.05 v1(37.29,14.48)
DM388_DDR0_DQS0: length 18.8
  TOP w0.102: U6.F3 v1(29.91,20.95) ; v1(39.78,19.3) 39.81,19.34 U7.AL11
  L03_SIG1 w0.102: v1(39.78,19.3) 39.73,19.36 39.73,20.23 39.18,20.78 35.45,20.78 35.15,20.47 31.34,20.47 30.96,20.09 29.81,20.09 29.48,19.76 27.9,19.76 27.79,19.87 27.79,20.15 27.86,20.21 29.15,20.21 29.46,20.52 30.39,20.52 30.49,20.62 30.49,20.81 30.35,20.95 v1(29.91,20.95)
DM388_DDR0_DQS0N: length 18.8
  TOP w0.102: U6.G3 v1(29.11,20.95) ; v1(39.22,19.3) 39.63,19.71 39.93,19.71 40.01,19.64 40.69,19.64 40.98,19.35 U7.AK11
  L03_SIG1 w0.102: v1(39.22,19.3) 39.4,19.48 39.4,20.09 39.04,20.45 35.59,20.45 35.28,20.14 31.47,20.14 31.09,19.76 29.95,19.76 29.62,19.43 27.77,19.43 27.46,19.74 27.46,20.28 27.72,20.54 29.01,20.54 29.11,20.64 v1(29.11,20.95)
DM388_DDR0_DQS1: length 13.9
  TOP w0.102: U7.AL15 40.44,17.3 40.08,17.3 40.06,17.28 39.49,17.28 39.12,17.65 38.94,17.65 38.87,17.73 37.43,17.73 37.16,17.46 37.16,17.33 37.06,17.23 36.89,17.23 36.83,17.29 36.83,17.61 36.56,17.89 36.21,17.89 35.92,17.6 35.92,15.93 35.87,15.88 35.59,15.88 35.53,15.94 35.53,18.23 34.66,19.1 33.29,19.1 33.01,18.83 33.01,18.38 32.79,18.15 U6.C7
DM388_DDR0_DQS1N: length 13.9
  TOP w0.102: U7.AK15 40.98,17.33 40.71,17.06 40.08,17.06 40.06,17.08 39.41,17.08 39.04,17.45 37.55,17.45 37.44,17.35 37.44,17.21 37.18,16.95 36.78,16.95 36.55,17.17 36.55,17.5 36.44,17.61 36.32,17.61 36.2,17.48 36.2,15.81 35.99,15.6 35.47,15.6 35.25,15.82 35.25,18.12 34.54,18.82 33.4,18.82 33.29,18.71 33.29,18.37 U6.B7
DM388_DDR0_DQS2: length 23.7
  TOP w0.102: U7.AL17 40.4,16.42 39.2,16.42 39.19,16.41 39.13,16.41 39.06,16.34 38.68,16.34 38.61,16.41 38.22,16.41 37.91,16.11 37.91,15.68 37.21,14.98 37.05,14.98 36.52,14.45 32.69,14.45 32.56,14.33 32.56,14 32.67,13.89 35.46,13.89 35.81,13.55 35.81,10.66 35.5,10.35 29.66,10.35 29.52,10.49 29.52,10.69 29.62,10.8 30.26,10.8 30.33,10.87 30.33,11.18 U8.F3
DM388_DDR0_DQS2N: length 23.6
  TOP w0.102: U8.G3 29.91,11.58 30.53,11.58 30.74,11.38 30.74,10.82 30.92,10.63 35.38,10.63 35.53,10.78 35.53,13.43 35.35,13.62 32.55,13.62 32.28,13.88 32.28,14.44 32.41,14.57 32.58,14.73 36.4,14.73 36.93,15.26 37.1,15.26 37.63,15.8 37.63,16.22 38.1,16.69 38.72,16.69 38.79,16.62 39.11,16.62 39.11,16.62 40.69,16.62 40.7,16.61 40.71,16.61 U7.AK17
DM388_DDR0_DQS3: length 15.9
  TOP w0.102: U7.AL20 40.4,14.92 39.77,14.92 39.25,14.4 39.07,14.4 38.99,14.32 38.92,14.32 36.93,12.33 36.93,10.2 36,9.27 35.52,9.27 35.42,9.17 35.42,8.67 35.15,8.41 34.72,8.41 34.45,8.67 34.45,9.17 34.25,9.37 33.18,9.37 33.07,9.27 33.07,9.09 33.18,8.99 33.62,8.99 33.89,8.73 33.89,7.72 33.76,7.6 33.11,7.6 U8.C7
DM388_DDR0_DQS3N: length 15.9
  TOP w0.102: U7.AK20 40.7,15.12 39.68,15.12 39.17,14.6 38.81,14.6 36.65,12.45 36.65,10.31 35.89,9.55 35.4,9.55 35.14,9.29 35.14,8.79 35.04,8.69 34.83,8.69 34.73,8.79 34.73,9.29 34.37,9.65 33.06,9.65 32.8,9.39 32.8,8.98 33.06,8.71 33.51,8.71 33.61,8.61 33.61,8.46 33.53,8.38 33.25,8.38 33.15,8.28 33.15,8.1 33.26,7.99 U8.B7
DM388_DDR0_ODT0: length 49.1
  TOP w0.102: U6.K1 v1(27.52,23.36) ; U8.K1 v1(26.71,13.19) ; U7.AL21 v1(40,14.34)
  L06_SIG2 w0.102: v1(40,14.34) 40.47,13.87 40.47,12.99 39.54,12.07 36.99,12.07 33.2,8.28 32.44,8.28 32.31,8.41 32.31,9.07 32.13,9.25 31.63,9.25 31.45,9.07 31.45,8.41 31.32,8.28 31.07,8.28 30.97,8.38 30.97,9.96 30.86,10.06 30.66,10.06 30.56,9.96 30.56,8.38 30.46,8.28 30.23,8.28 30.13,8.38 30.13,9.91 30,10.03 29.63,10.03 29.53,9.93 29.53,9.27 29.42,9.17 29.22,9.17 29.12,9.27 29.12,9.93 29.02,10.03 27.05,10.03 26.93,9.91 26.93,9.35 26.8,9.22 26.17,9.22 25.96,9.42 25.96,10.95 26.12,11.1 26.93,11.1 27.11,11.28 27.11,12.8 v1(26.71,13.19) 27.67,13.19 28.43,13.95 28.43,17.33 28.72,17.62 28.72,17.93 28.12,18.53 28.12,19.5 28.02,19.6 27.92,19.6 27.82,19.7 27.82,19.91 27.92,20.01 28.02,20.01 28.12,20.11 28.12,20.6 27.13,21.59 27.13,22.97 v1(27.52,23.36)
  BOTTOM w0.102: RA6.5 26.94,24.5 27.16,24.72 27.87,24.72 27.99,24.59 27.99,23.44 27.87,23.32 27.56,23.32 v1(27.52,23.36)
DM388_DDR0_RASN: length 49.4
  TOP w0.102: U8.J3 v1(27.51,11.59) ; U7.AJ25 41.48,11.85 v1(41.49,11.83) ; U6.J3 v1(27.51,21.75)
  L03_SIG1 w0.102: v1(41.49,11.83) 41.87,11.45 41.87,10.72 41.89,10.71 41.89,9.45 41.76,9.32 41.08,9.32 40.8,9.6 40.8,10.08 40.26,10.62 37.6,10.62 36.25,9.27 36.25,7.19 37.15,6.29 37.15,5.5 36.38,4.73 27.46,4.73 26.58,5.61 26.56,5.61 26.33,5.83 26.33,5.85 26.33,5.86 26.33,7.71 26.13,7.92 26.13,9.77 27.51,11.15 v1(27.51,11.59)
  L06_SIG2 w0.102: v1(27.51,11.59) 28.73,12.81 28.73,17.34 28.92,17.53 28.92,18.02 28.38,18.56 28.38,22.29 28.25,22.42 28.05,22.42 27.94,22.31 27.94,22.18 v1(27.51,21.75)
  BOTTOM w0.102: RA6.6 26.44,23.36 27.1,22.71 27.1,21.85 27.2,21.75 v1(27.51,21.75)
DM388_DDR0_RST: length 49.3
  TOP w0.102: R72.2 20.38,22.93 20.48,22.83 20.48,22.45 20.58,22.35 20.78,22.35 20.89,22.45 20.89,22.83 20.99,22.93 21.54,22.93 v1(21.91,22.55) U6.T2 ; U7.AA20 45.45,14.81 v1(45.01,14.81) ; U8.T2 v1(21.91,12.39)
  L03_SIG1 w0.102: v1(21.91,12.39) 21.61,12.09 20.71,12.09 20.53,12.27 20.53,16.75 21.13,17.35 21.13,17.84 21.1,17.87 21.1,17.9 20.7,18.3 20.7,21.34 v1(21.91,22.55)
  BOTTOM w0.102: v1(21.91,12.39) 21.44,12.87 21.44,14.66 21.7,14.91 30.83,14.91 31.13,15.22 31.13,17.11 31.37,17.35 35.46,17.35 35.83,16.98 35.83,16.34 36.62,15.56 36.62,14.39 37.16,13.85 38.67,13.85 39.76,14.94 43.96,14.94 44.28,15.27 44.58,15.27 44.82,15.03 44.82,15 v1(45.01,14.81)
DM388_DDR0_VTP: length 1.5
  TOP w0.102: U7.AL30 40.29,9.84 v1(40.03,9.59)
  BOTTOM w0.102: v1(40.03,9.59) 40.26,9.81 R122.1
DM388_DDR0_WEN: length 49.4
  TOP w0.102: U8.L3 v1(25.91,11.59) ; U6.L3 v1(25.91,21.75) ; v1(39.98,11.74) 40.09,11.84 U7.AL26
  L03_SIG1 w0.102: v1(25.91,21.75) 25.5,21.33 25.5,20.7 25.6,20.6 26.01,20.6 26.12,20.5 26.12,20.3 26.01,20.2 25.6,20.2 25.5,20.09 25.5,19.89 25.6,19.79 26.01,19.79 26.12,19.69 26.12,19.48 26.01,19.38 25.6,19.38 25.5,19.28 25.5,16.77 26.01,16.26 26.01,15.55 26.33,15.23 26.33,12.01 v1(25.91,11.59)
  BOTTOM w0.102: v1(39.98,11.74) 39.72,12 39.09,12 38.89,11.8 38.89,11.48 38.66,11.25 38.1,11.25 36.84,9.99 32.82,9.99 32.72,9.89 32.72,9.68 32.82,9.58 36.15,9.58 36.25,9.48 36.25,9.27 36.15,9.17 33.28,9.17 33.15,9.05 33.15,8.87 33.25,8.76 36.15,8.76 36.25,8.66 36.25,8.43 36.15,8.33 32.87,8.33 32.72,8.48 32.72,9.02 32.22,9.51 31.46,9.51 30.18,10.8 26.06,10.8 25.91,10.95 v1(25.91,11.59) ; RA10.6 26.67,20.37 26.78,20.47 26.78,21.21 26.67,21.31 25.99,21.31 25.91,21.38 v1(25.91,21.75)
DM388_EMU0: length 40.8
  TOP w0.14: R78.2 60.66,14.83 60.84,15.01 60.96,15.01 61.72,15.77 61.72,16.01 v1(62.03,16.33)
  L06_SIG2 w0.119: v1(62.03,16.33) 62.03,16.96 61.51,17.49 61.51,18.15 63.09,19.73 63.09,23.53 63.56,23.99 63.57,23.99 64.59,25.02 65.94,25.02 66.89,25.02 69.16,27.3 73.89,27.3 74.65,28.05 75.45,28.05 77.34,29.94 77.34,30.99 75.82,32.51 73.75,32.51 73.72,32.48 71.1,32.48 v1(69.45,34.14)
  BOTTOM w0.14: v1(69.45,34.14) 69.36,34.23 J3.30
DM388_EMU1: length 39.8
  TOP w0.14: R77.2 60.16,16.13 60.32,15.97 v1(60.77,15.97)
  L06_SIG2 w0.119: v1(70.34,33.97) 70.78,33.97 70.83,33.91 72.92,33.91 73.14,34.14 73.49,34.14 73.79,33.84 73.79,33.55 74.47,32.88 75.84,32.88 77.56,31.16 77.56,29.83 74.82,27.09 74.53,27.09 74.47,27.03 69.24,27.03 67.03,24.82 67.03,23.35 64.45,20.77 64.07,20.38 64.07,20.2 64.07,19.17 62.77,17.88 62.77,17.79 62.62,17.64 62.62,16.37 62.02,15.77 61.05,15.77 60.84,15.97 v1(60.77,15.97)
  BOTTOM w0.14: v1(70.34,33.97) 69.89,33.97 69.64,33.73 J3.32
DM388_GMII_COL: length 37.6
  TOP w0.102: U7.AH1 41.98,25.31 41.96,25.32 v1(41.96,25.76)
  L06_SIG2 w0.102: 40.72,26.59 40.72,26.33 41.29,25.76 v1(41.96,25.76)
  L06_SIG2 w0.119: 40.72,26.59 40.72,27.56 35.98,32.29 31.98,32.29 30.49,33.78 28.39,33.78 28.38,33.79 28.06,33.79 28.05,33.78 27.83,33.78 27.33,33.28 23.89,33.28 23.61,33 15.42,33 14.34,31.92 v1(14.34,31.48)
  BOTTOM w0.14: v1(14.34,31.48) 14.11,31.48 13.59,30.96 12.26,30.96 12.25,30.95 11.4,30.95 J4.54
DM388_GMII_CRS: length 37.8
  TOP w0.102: v1(39.98,25.86) 41.25,25.86 41.7,25.41 41.7,24.22 41.71,24.21 41.71,24.11 U7.AH2
  L03_SIG1 w0.102: v1(39.98,25.86) 39.02,25.86
  L03_SIG1 w0.119: v1(9.95,20.33) 10.68,20.33 12.68,22.33 14.8,22.33 16.72,24.25 18.67,24.25 19.76,25.35 29.46,25.35 30.07,24.74 31.09,24.74 32.03,25.68 33.2,25.68 33.48,25.96 38.92,25.96 39.02,25.86
  BOTTOM w0.14: J4.14 v1(9.95,20.33)
DM388_GMII_GMTCLK: length 35
  TOP w0.14: v1(36.85,22.66) 36.85,22.66 36.86,22.66 36.96,22.56 R73.1
  L03_SIG1 w0.102: 38.94,24.37 39.06,24.25 39.06,23.09 38.94,22.97
  L03_SIG1 w0.119: 38.94,22.97 38.84,22.87 38.59,22.87 38.47,22.99 38.47,23.96 38.35,24.07 38.11,24.07 37.99,23.96 37.99,22.99 37.88,22.87 37.55,22.87 37.45,22.97 37.45,23.72 37.28,23.88 37,23.88 36.86,23.75 36.86,23.11 36.85,23.1 v1(36.85,22.66) ; 38.94,24.37 38.84,24.47 38.55,24.47 38.43,24.59 38.43,25.39 38.31,25.51 38.07,25.51 37.95,25.39 37.95,24.59 37.84,24.47 37.6,24.47 37.48,24.59 37.48,25.39 37.36,25.51 37.12,25.51 37,25.39 37,24.6 36.88,24.48 33.83,24.48 33.81,24.45 31.26,24.45 31.22,24.42 29.93,24.42 29.93,24.42 29.08,24.42 28.47,25.02 19.97,25.02 v1(18.59,23.64)
  BOTTOM w0.14: J4.25 17.7,23.33 17.73,23.3 18.07,23.3 18.09,23.32 18.27,23.32 v1(18.59,23.64)
DM388_GMII_MTCLK: length 37.5
  TOP w0.102: U7.AG4 42.03,22.84 v1(41.93,22.74)
  L03_SIG1 w0.119: v1(41.93,22.74) 41.76,22.9 41.28,22.9 41.09,22.71 41.09,21.7 40.96,21.57 40.74,21.57 40.61,21.7 40.61,23.66 40.72,23.77 41.51,23.77 41.64,23.9 41.64,24.13 41.5,24.28 40.24,24.28 40.12,24.16 40.12,21.75 39.94,21.57 39.49,21.57 39.26,21.8 39.26,21.94 38.72,22.49 37.26,22.49 37.02,22.25 36.68,22.25 36.67,22.25 36.47,22.25 36.32,22.4 36.32,22.97 35.51,23.78 31.49,23.78 28.27,23.78 27.67,24.38 20.8,24.38 19.99,23.57 19.99,23.41 20.18,23.22 20.18,23.05 20.01,22.88 19.84,22.88 19.65,23.07 19.48,23.07 18.83,22.41 18.8,22.41 18.49,22.1 18.49,22.01 18.37,21.89 v1(18.19,21.89)
  BOTTOM w0.14: v1(18.19,21.89) 18.15,21.89 18.06,21.98 17.7,21.98 17.54,21.83 J4.19
DM388_GMII_RCLK: length 34.3
  L06_SIG2 w0.119: v1(36.68,27.5) 36.68,27.47 36.39,27.18 36.22,27.18 36.12,27.28 36.12,28.37 36,28.49 35.77,28.49 35.65,28.37 35.65,27.24 35.53,27.12 35.27,27.12 35.15,27.24 35.15,28.31 35.03,28.43 34.2,28.43 34.1,28.53 33.98,28.53 33.73,28.77 33.73,28.88 33.61,29 33.16,29 33.04,29.12 33.04,29.81 32.92,29.93 32.68,29.93 32.56,29.81 32.56,29.28 32.47,29.19 32.16,29.19 32.07,29.29 32.07,29.86 31.99,29.93 31.59,29.93 31.49,29.84 31.49,29.33 31.38,29.21 31.14,29.21 31.02,29.33 31.02,29.84 30.92,29.93 30.63,29.93 30.54,29.84 30.54,29.33 30.39,29.17 30.22,29.17 30.06,29.33 30.06,29.84 29.97,29.93 29.68,29.93 29.58,29.84 29.58,29.33 29.43,29.17 29.26,29.17 29.11,29.33 29.11,29.84 29.01,29.93 28.85,29.93 28.01,29.09 26.31,29.09 25.91,28.7 19.18,28.7 19.06,28.58 19.06,28.34 19.49,27.92 v1(19.49,27.33)
  BOTTOM w0.14: J4.39 19.48,27.33 v1(19.49,27.33) ; v1(36.68,27.5) 37.13,27.5 37.42,27.22 37.42,26.55 37.89,26.07 37.89,26.04 R106.2
DM388_GMII_RXD[0]: length 33.7
  L06_SIG2 w0.119: v1(36.74,26.8) 35.84,26.8 35.84,26.8 35.13,26.8 34.83,27.11 34.83,27.82 34.53,28.11 34.06,28.11 33.96,28.21 33.83,28.21 33.35,28.68 33.05,28.68 32.93,28.56 32.93,28.31 32.78,28.16 32.61,28.16 32.46,28.31 32.46,28.75 32.34,28.87 32.1,28.87 31.98,28.75 31.98,28.31 31.86,28.19 31.62,28.19 31.5,28.31 31.5,28.77 31.38,28.89 31,28.89 30.88,29.01 30.68,29.01 30.52,28.85 30.08,28.85 29.93,29.01 29.72,29.01 29.56,28.85 28.65,28.85 28.5,28.7 28.5,28.21 28.38,28.09 28.11,28.09 27.99,28.21 27.99,28.55 27.82,28.73 26.56,28.73 26.27,28.43 26.11,28.43 25.67,28 25.67,27.42 25.56,27.3 25.32,27.3 25.2,27.42 25.2,28.25 25.08,28.37 23.78,28.37 23.66,28.25 23.66,27.52 23.54,27.4 23.3,27.4 23.18,27.52 23.18,28.28 23.09,28.37 22.75,28.37 22.66,28.28 22.66,28.17 22.54,28.05 22.3,28.05 22.18,28.17 22.18,28.2 22.06,28.32 21.83,28.32 21.71,28.2 21.71,27.98 21.59,27.86 21.36,27.86 21.23,27.99 21.23,28.25 21.11,28.37 19.94,28.37 19.85,28.28 19.85,27.91 19.96,27.79 v1(20.6,27.79)
  BOTTOM w0.14: v1(36.74,26.8) 36.74,25.81 37.59,24.96 R109.2 ; v1(20.6,27.79) 20.28,28.11 19.85,28.11 18.63,29.33 J4.47
DM388_GMII_RXD[1]: length 37.2
  TOP w0.102: v1(39.7,26.34) 39.02,25.66 39.02,24.86 39.6,24.28 40.04,24.28 U7.AL2
  L06_SIG2 w0.102: 38.94,26.04 39.4,26.04 v1(39.7,26.34)
  L06_SIG2 w0.119: 38.94,26.04 38.64,26.04 37.88,26.8 37.88,28.52 35.92,30.48 28.63,30.48 27.83,29.68 26.06,29.68 25.72,29.34 19.06,29.34 18.81,29.59 18.81,30.33 18.69,30.45 15.41,30.45 15.28,30.33 15.28,29.71 15.47,29.51 17.78,29.51 v1(18.09,29.83)
  BOTTOM w0.14: J4.49 v1(18.09,29.83)
DM388_GMII_RXD[2]: length 37.3
  TOP w0.102: 38.94,24.46 39.33,24.07 39.5,24.07 39.5,24.06 39.55,24.06 39.56,24.05 39.76,24.05 U7.AL3 ; 39.11,26.59 38.94,26.43
  TOP w0.14: 38.94,24.46 38.59,24.82 38.59,26.07 38.94,26.43 ; v1(39.24,26.73) 39.11,26.59
  L06_SIG2 w0.119: v1(18.88,31.34) 18.52,31.7 18.52,32.34 18.64,32.46 18.91,32.46 19.03,32.34 19.03,31.99 19.15,31.87 19.39,31.87 19.5,31.99 19.5,32.34 19.62,32.46 19.99,32.46 20.11,32.34 20.11,31.32 19.95,31.17 19.64,31.17 19.41,30.94 19.41,30.1 19.58,29.93 22.12,29.93 22.24,30.05 22.24,30.47 22.36,30.59 22.57,30.59 22.71,30.45 22.71,30.05 22.91,29.85 25.45,29.85 25.84,30.23 27.75,30.23 28.44,30.92 36.1,30.92 38.43,28.59 38.43,27.51 38.91,27.04 38.93,27.04 v1(39.24,26.73)
  BOTTOM w0.14: v1(18.88,31.34) 17.86,30.33 J4.51
DM388_GMII_RXD[3]: length 37.5
  TOP w0.102: 38.94,23.98 39.06,23.86 39.47,23.86 40.28,23.04 40.7,23.04 40.98,23.32 U7.AK3
  TOP w0.14: 38.94,23.98 38.1,24.82 38.1,26.39 v1(38.54,26.82)
  L06_SIG2 w0.119: v1(38.54,26.82) 38.16,27.2 38.16,28.55 36.01,30.7 28.54,30.7 28.1,30.27 27.79,29.96 25.95,29.96 25.59,29.59 19.36,29.59 19.12,29.82 19.12,30.55 18.88,30.8 15.5,30.8 15.36,30.94 15.36,31.28 15.48,31.4 v1(18.11,31.4)
  BOTTOM w0.14: v1(18.11,31.4) 17.54,30.83 J4.53
DM388_GMII_RXD[4]: length 37.4
  TOP w0.102: v1(39.45,23.31) 39.76,23 39.79,23 39.95,22.84 U7.AK4
  L06_SIG2 w0.102: v1(39.45,23.31) 40.18,23.31 41.41,24.54 41.41,25.18 40.11,26.47 40.11,26.59
  L06_SIG2 w0.119: 40.11,26.59 39.56,27.14 39.21,27.14 39.04,27.31 39.02,27.31 38.71,27.62 38.71,28.62 36.11,31.23 24.34,31.23 24.03,30.92 21.03,30.92 20.38,31.57 20.38,32.57 20.26,32.69 16.69,32.69 16.57,32.57 16.57,32.28 16.72,32.13 v1(18.11,32.13)
  BOTTOM w0.14: J4.57 17.92,32.33 v1(18.11,32.13)
DM388_GMII_RXD[5]: length 30.2
  L06_SIG2 w0.119: v1(14.85,33.19) 15.67,34 21.9,34 22.02,33.88 22.02,33.4 22.14,33.28 22.38,33.28 22.5,33.4 22.5,33.88 22.62,34 23.46,34 23.82,33.64 27.05,33.64 27.71,34.31 32.4,34.31 v1(32.71,34)
  BOTTOM w0.14: v1(14.85,33.19) 15.21,32.83 J4.59 ; v1(32.71,34) 37.93,28.78 R104.2
DM388_GMII_RXD[6]: length 35.7
  L06_SIG2 w0.119: v1(20.86,32.26) 21.3,32.26 21.66,31.89 23.96,31.89 24.08,32.01 24.08,32.24 24.23,32.39 24.41,32.39 24.56,32.24 24.56,32.01 24.72,31.85 28.46,31.85 28.62,32.01 28.62,32.89 28.74,33.01 28.98,33.01 29.1,32.89 29.1,32.01 29.22,31.89 29.45,31.89 29.57,32.01 29.57,32.89 29.69,33.01 29.93,33.01 30.05,32.89 30.05,32.01 30.17,31.89 36.07,31.89 39.8,28.16 39.8,27.85 v1(40.11,27.53)
  BOTTOM w0.102: R111.2 40.75,23.71 41.61,24.57 41.61,25.08 41.15,25.54 41.15,25.95 40.77,26.33 40.77,26.33 40.52,26.59 40.52,26.59
  BOTTOM w0.14: v1(20.86,32.26) 19.08,32.26 18.01,33.33 J4.61 ; v1(40.11,27.53) 40.11,27 40.52,26.59
DM388_GMII_RXD[7]: length 34.5
  L06_SIG2 w0.119: v1(39.33,27.61) 39.33,28.32 36.15,31.5 v1(21.11,31.5)
  BOTTOM w0.102: 40.56,26.09 40.9,25.75 40.9,25.5 41.41,25 41.41,24.68 40.62,23.9 39.55,23.9 39.27,24.19 38.94,24.19
  BOTTOM w0.14: J4.63 18.15,33.83 19.31,32.66 21.02,32.66 21.37,32.32 21.37,31.75 v1(21.11,31.5) ; R110.2 37.79,24.02 37.96,24.19 38.94,24.19 ; 40.56,26.09 39.64,27.01 39.64,27.3 v1(39.33,27.61)
DM388_GMII_RXDV: length 37.4
  TOP w0.102: U7.AJ6 v1(41.48,22.38)
  L06_SIG2 w0.102: v1(41.48,22.38) 40.84,21.74 39.33,21.74 38.94,22.13
  L06_SIG2 w0.119: v1(18.01,27.83) 17.7,28.14 16.61,28.14 16.45,27.98 16.45,27.69 16.58,27.56 17.09,27.56 17.21,27.44 17.21,26.45 17.38,26.28 18.23,26.28 18.55,26.59 21.91,26.59 22.01,26.49 22.37,26.49 22.46,26.58 28.48,26.58 28.54,26.64 28.85,26.64 29.04,26.82 30.41,26.82 31.1,27.51 31.42,27.51 31.54,27.39 31.54,26.04 31.66,25.93 31.89,25.93 32.01,26.04 32.01,27.39 32.13,27.51 32.92,27.51 33.49,26.94 34.43,26.94 34.43,26.94 34.56,26.94 34.97,26.53 36.36,26.53 36.36,26.53 36.51,26.38 37.14,26.38 38.69,24.83 38.69,22.38 38.94,22.13
  BOTTOM w0.14: J4.41 v1(18.01,27.83)
